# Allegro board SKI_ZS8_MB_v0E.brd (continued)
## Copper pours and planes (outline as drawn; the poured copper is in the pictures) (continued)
DDR_VTTREF on TOP (solid shape): 197.87,58.57 197.87,57.56 197.79,57.48 197.33,57.48 197.23,57.58 197.23,57.68 196.24,58.67 196.14,58.67 195.99,58.83 195.99,59.61 196.01,59.64 196.8,59.64
ECAGND on TOP (solid shape): 46.86,28.96 46.86,27.18 46.74,27.05 44.58,27.05 43.05,28.57 43.05,28.92 43.12,29.15 43.05,29.38 43.05,29.46 43.37,29.78 43.45,29.81 43.52,29.77 44.02,29.7 44.1,30.19 44.09,30.3 44.18,30.35 45.47,30.35
L_SPK+ on TOP (solid shape): 22.4,7.47 22.4,6.83 22.17,6.6 19.56,6.6 19.3,6.86 19.3,7.75 19.43,7.87 22,7.87
L_SPK+ on IN3 (solid shape): 33.45,16.92 33.45,15.47 33.16,15.18 32.58,15.18 32.44,15.32 32.44,16.31 33.15,17.02 33.35,17.02
L_SPK+ on IN3 (solid shape): 23.11,7.87 23.11,6.98 22.99,6.86 22.48,6.86 22.24,6.83 22.02,6.73 20.83,6.73 20.45,7.11 20.45,7.75 20.7,8 22.99,8
L_SPK- on TOP (solid shape): 19.3,6.2 19.34,6.24 19.39,6.23 19.4,6.22 22.17,6.22 22.43,5.96 22.43,5.4 22.23,5.21 19.56,5.21 19.3,5.46
L_SPK- on IN3 (solid shape): 22.99,6.22 22.99,5.33 22.86,5.21 20.57,5.21 20.32,5.46 20.32,6.1 20.57,6.35 22.86,6.35
L_SPK- on IN3 (solid shape): 34.51,17.08 34.51,15.15 34.5,15.15 34.8,14.85 34.8,14.35 34.54,14.1 33.91,14.1 33.83,14.17 33.83,17.07 33.99,17.22 34.37,17.22
LCD_VCC on TOP (solid shape): 25.32,77.94 25.45,77.92 25.59,77.94 28.56,77.94 30.31,76.19 32.31,76.19 32.96,75.55 32.96,74.69 32.72,74.46 26.1,74.46 25.52,75.05 23.26,75.05 23.01,75.3 21.73,75.3 20.39,76.65 20.39,77.79 20.54,77.94
LCD_VCC on BOTTOM (solid shape): 32.84,77.71 32.84,76.24 32.79,76.19 32.79,75.15 32.44,74.79 31.14,74.79 30.86,75.07 30.86,75.66 31.62,76.42 32.62,76.42 32.62,77.54 32.36,77.54 32.36,76.42 32.11,76.42 32.11,77.53 32.11,77.54 31.85,77.54 31.85,76.42 31.62,76.42 31.62,77.76 31.65,77.79 32.77,77.79
LCD_VCC_S on TOP (solid shape): 19.11,82.63 19.11,81.39 19.43,81.07 19.43,78.49 19.81,78.11 19.81,76.58 19.68,76.45 18.54,76.45 18.53,76.47 18.08,76.47 17.64,76.9 17.64,80.56 18.58,81.5 18.58,82.63 18.75,82.8 18.94,82.8
LCD_VIN on TOP (solid shape): 23.18,74.99 23.18,72.97 23.98,72.17 23.98,66.23 23.72,65.98 23.09,65.98 22.87,66.05 22.65,65.98 21.92,65.98 21.67,66.23 21.67,70.03 21.66,70.03 21.66,70.56 21.72,70.63 21.74,70.72 21.74,71.02 21.7,71.14 21.59,71.21 20.01,72.8 20.01,74.95 20.26,75.2 22.97,75.2
LCD_VIN on BOTTOM (solid shape): 27.36,77.81 27.36,74.89 25.96,73.49 25.92,73.46 25.89,73.46 25.87,73.46 25.84,73.47 25.82,73.48 25.78,73.54 25.75,73.58 25.72,73.62 25.68,73.66 25.63,73.69 25.58,73.71 25.53,73.72 25.48,73.73 25.43,73.73 25.38,73.72 25.33,73.7 25.28,73.67 25.24,73.64 25.2,73.61 25.17,73.56 25.14,73.52 25.12,73.47 25.11,73.42 25.11,73.36 25.11,73.31 25.12,73.27 25.12,73.24 25.11,73.21 25.09,73.19 25.07,73.17 25.04,73.16 25.02,73.16 22.71,73.16 22.5,73.37 22.5,75.32 22.68,75.5 24.72,75.5 25.6,76.39 25.6,76.43 27.11,76.43 27.11,77.53 26.86,77.53 26.86,76.43 26.61,76.43 26.61,77.53 26.36,77.53 26.36,76.43 26.11,76.43 26.11,77.53 25.86,77.53 25.86,76.43 25.6,76.43 25.6,77.87 25.75,77.94 27.23,77.94
R_SPK+ on TOP (solid shape): 19.38,3.5 19.42,3.52 19.45,3.5 19.53,3.43 21.75,3.43 21.84,3.33 21.84,2.67 21.59,2.41 19.68,2.41 19.3,2.79 19.3,3.43
R_SPK+ on IN3 (solid shape): 22.86,3.3 22.86,2.41 22.61,2.16 20.57,2.16 20.19,2.54 20.19,3.17 20.45,3.43 22.73,3.43
R_SPK+ on IN3 (solid shape): 36.34,17.13 36.49,17.05 36.67,17.05 37.83,15.89 37.83,15.76 37.52,15.44 36.81,15.44 36.2,16.06 36.2,16.74 36.19,16.87 36.16,17.03 36.27,17.14 36.33,17.14
R_SPK- on TOP (solid shape): 19.3,4.8 19.34,4.85 19.39,4.83 19.4,4.83 22.28,4.83 22.42,4.69 22.42,3.86 22.36,3.81 19.68,3.81 19.3,4.19
R_SPK- on IN3 (solid shape): 23.11,4.7 23.11,3.94 22.99,3.81 22.35,3.81 22.33,3.81 20.57,3.81 20.45,3.94 20.45,4.57 20.7,4.83 22.99,4.83
R_SPK- on IN3 (solid shape): 35.76,17.98 35.76,15.83 35.91,15.69 35.91,15.36 35.8,15.26 35.22,15.26 34.98,15.5 34.98,17.78 35.23,18.03 35.71,18.03
RING2 on TOP (solid shape): 22.63,25.63 22.63,24.36 22.38,24.1 20.73,24.1 20.6,24.23 20.6,25.63 20.85,25.88 22.38,25.88
RING2 on BOTTOM (solid shape): 36.35,26.52 36.35,25.1 36.17,24.92 34.85,24.92 34.75,25.02 34.75,25.5 35.31,26.06 35.31,26.59 35.36,26.64 36.22,26.64
RING2 on IN3 (solid shape): 22.63,25.63 22.63,24.36 22.38,24.1 20.73,24.1 20.6,24.23 20.6,25.63 20.85,25.88 22.38,25.88
RING2 on IN3 (solid shape): 36.35,26.52 36.35,25.1 36.17,24.92 34.85,24.92 34.75,25.02 34.75,25.5 35.31,26.06 35.31,26.59 35.36,26.64 36.22,26.64
RING2_R on TOP (solid shape): 20.22,26.01 20.22,24.69 19.86,24.33 19.18,24.33 18.94,24.57 16.95,24.57 16.64,24.89 16.64,25.91 16.84,26.11 20.12,26.11
RING2_R on IN3 (solid shape): 18.95,26.52 18.95,25.25 18.69,24.99 17.04,24.99 16.66,25.37 16.66,26.39 17.04,26.77 18.69,26.77
SLEEVE on TOP (solid shape): 22.81,17.32 22.81,16.69 22.43,16.31 20.65,16.31 20.4,16.56 20.4,17.45 20.78,17.83 22.3,17.83
SLEEVE on BOTTOM (solid shape): 34.29,26.67 34.75,26.67 34.82,26.59 34.82,26.03 33.91,25.12 33.01,25.12 32.35,25.78 32.35,26.75 32.39,26.79 33.66,26.79 33.66,26.8 34.16,26.8
SLEEVE on IN3 (solid shape): 24.46,17.45 24.46,16.69 24.21,16.43 21.79,16.43 21.41,16.81 21.41,17.7 21.79,18.08 23.83,18.08
SLEEVE on IN3 (solid shape): 34.29,26.42 34.29,25.4 34.16,25.27 32.26,25.27 32,25.53 32,26.42 32.38,26.8 33.91,26.8
SLEEVE_R on TOP (solid shape): 20.02,17.42 20.02,16.03 19.82,15.83 17.99,15.83 17.44,16.38 17.09,16.38 16.94,16.54 16.94,17.25 17.01,17.31 18.94,17.31 19.09,17.46 19.98,17.46
SLEEVE_R on IN3 (solid shape): 19.25,16.81 19.25,15.67 19,15.42 17.73,15.42 17.35,15.8 17.35,16.69 17.6,16.94 19.13,16.94
SPK_L+ on TOP (solid shape): 17.12,8 17.14,8 17.15,7.98 17.63,7.73 18.16,7.85 18.19,7.86 18.21,7.85 18.49,7.74 18.78,7.73 18.79,7.74 18.81,7.73 18.92,7.62 18.92,6.73 18.8,6.6 15.04,6.6 14.93,6.72 14.93,7.81 15.11,8
SPK_L+ on BOTTOM (solid shape): 18.03,9.27 18.03,8.89 17.99,8.81 17.89,8.8 17.37,8.48 17.89,8.16 17.99,8.16 18.03,8.07 18.03,6.98 17.65,6.6 16.81,6.6 16.45,6.97 16.45,9.46 16.51,9.52 17.78,9.52
SPK_L- on TOP (solid shape): 18.75,6.22 18.78,6.21 18.8,6.17 18.8,5.46 18.67,5.33 14.94,5.33 14.87,5.4 14.87,6.11 14.99,6.22
SPK_L- on BOTTOM (solid shape): 15.99,9.49 15.99,6.89 16.66,6.22 17.25,6.22 17.48,5.99 17.48,5.51 17.25,5.28 15.78,5.28 15.21,5.86 15.21,9.49 15.22,9.5 15.24,9.5 15.98,9.5
SPK_R+ on TOP (solid shape): 18.8,3.3 18.8,2.79 18.54,2.54 15.11,2.54 14.9,2.75 14.9,3.44 15.01,3.56 18.54,3.56
SPK_R+ on BOTTOM (solid shape): 13.49,9.45 13.49,4.34 14.38,3.45 17.09,3.45 17.35,3.2 17.35,2.34 17.22,2.21 14.05,2.21 12.67,3.58 12.67,9.47 12.7,9.5 13.44,9.5
SPK_R- on TOP (solid shape): 18.75,4.95 18.78,4.94 18.8,4.9 18.8,4.06 18.67,3.94 14.99,3.94 14.85,4.07 14.85,4.89 14.91,4.95
SPK_R- on BOTTOM (solid shape): 14.74,9.51 14.74,5.78 15.62,4.9 16.94,4.9 17.14,4.7 17.14,4.03 16.95,3.84 14.99,3.84 13.96,4.86 13.96,9.52 14.73,9.52
VA on BOTTOM (solid shape): 198.12,60.64 199.96,60.64 200.15,60.45 200.15,56.26 199.77,55.88 195.71,55.88 195.58,56.01 195.58,56.9 195.81,57.13 196.24,57.13 196.47,57.35 196.47,60.11 197.31,60.11 197.31,60.05 197.33,59.99 197.35,59.94 197.36,59.91 197.36,59.21 197.36,59.19 197.36,59.13 197.37,59.07 197.38,59.01 197.4,58.96 197.43,58.91 197.47,58.86 197.51,58.82 197.56,58.79 197.61,58.76 197.67,58.74 197.72,58.73 197.78,58.72 197.84,58.73 197.9,58.74 197.95,58.76 198,58.78 198.05,58.81 198.1,58.85 198.13,58.9 198.17,58.94 198.19,59 198.21,59.05 198.22,59.11 198.22,59.17 198.22,59.23 198.2,59.28 198.18,59.34 198.17,59.36 198.17,60.09 198.17,60.12 198.17,60.18 198.16,60.24 198.14,60.29 198.11,60.35 198.07,60.4 198.03,60.44 197.99,60.48 197.94,60.51 197.88,60.53 197.82,60.55 197.76,60.55 197.7,60.55 197.65,60.54 197.59,60.53 197.53,60.5 197.48,60.47 197.44,60.43 197.4,60.39 197.37,60.34 197.34,60.29 197.32,60.23 197.31,60.17 197.31,60.11 196.47,60.11 196.47,60.58 196.63,60.74 198.02,60.74
VA1 on TOP (solid shape): 205.59,56.9 206.63,56.9 206.76,56.77 206.76,55.02 204.89,53.15 203.14,53.15 202.02,52.03 200.42,52.03 200.01,52.44 199.66,52.44 199.46,52.24 199.46,51.88 199.25,51.68 198.02,51.68 197.87,51.83 197.87,53.65 203.51,53.65 203.51,53.59 203.53,53.54 203.55,53.49 203.58,53.45 203.61,53.4 203.65,53.37 203.69,53.34 203.74,53.31 203.8,53.3 203.85,53.29 203.9,53.29 203.96,53.3 204.01,53.31 204.06,53.34 204.1,53.37 204.14,53.4 204.18,53.45 204.2,53.49 204.23,53.54 204.24,53.59 204.24,53.65 204.24,53.7 204.23,53.75 204.22,53.8 204.19,53.85 204.16,53.9 204.12,53.94 204.08,53.97 204.03,53.99 203.98,54.01 203.93,54.03 203.88,54.03 203.82,54.03 203.77,54.01 203.72,53.99 203.67,53.97 203.63,53.94 203.59,53.9 203.56,53.85 203.54,53.8 203.52,53.75 203.51,53.7 203.51,53.65 197.87,53.65 197.87,54.14 200.13,56.41 201.32,56.41 202,57.09 204.61,57.09 204.74,57.22 205.27,57.22
VA1 on BOTTOM (solid shape): 199.41,55.1 199.41,51.83 197.36,49.78 193.64,49.78 193.48,49.94 193.48,55.05 193.68,55.25 199.26,55.25
VA2 on BOTTOM (solid shape): 192.51,53.57 192.51,47.34 192.28,47.12 186.44,47.12 186.31,47.24 186.31,52.7 186.44,52.83 187.71,52.83 188.72,53.85 192.23,53.85
VRTC1 on TOP (solid shape): 82.45,46.74 82.45,45.82 82.68,45.59 82.68,44.15 82.58,44.04 81.53,44.04 81.15,44.42 81.15,46.74 81.41,46.99 82.2,46.99
VRTC1 on BOTTOM (solid shape): 81.89,46.85 82.49,46.85 82.55,46.79 82.55,45.97 82.42,45.85 81.28,45.85 81.25,45.87 80.73,45.87 80.41,46.19 80.41,46.73 80.67,46.99 81.75,46.99
VRTC2 on TOP (solid shape): 84.71,46.61 84.71,44.15 84.61,44.04 83.54,44.04 83.46,44.12 83.46,45.75 83.67,45.95 83.67,46.71 83.82,46.86 84.45,46.86
VRTC2 on BOTTOM (solid shape): 84.84,46.48 84.84,45.08 84.45,44.7 83.82,44.7 83.69,44.83 83.69,46.61 83.95,46.86 84.45,46.86
N03288 on TOP (solid shape): 206.76,60.33 206.76,58.04 206.19,57.47 203.2,57.47 203.07,57.6 203.07,58.67 204.98,60.58 206.5,60.58
N05646 on TOP (solid shape): 209.84,57.11 209.84,56.3 209.04,55.5 207.28,55.5 207.09,55.69 207.09,55.8 207.98,55.8 207.98,56.81 207.7,56.81 207.7,55.8 207.09,55.8 207.09,57.61 207.26,57.78 209.17,57.78
N05802 on BOTTOM (solid shape): 124.84,11.68 124.84,10.16 125.22,9.78 125.22,3.94 125.09,3.81 120.65,3.81 120.52,3.94 120.52,10.88 120.22,11.19 120.22,11.38 120.65,11.81 124.71,11.81
N90734 on BOTTOM (solid shape): 105.86,18.8 105.86,12.89 104.9,11.94 100.71,11.94 100.46,12.19 100.46,17.91 101.6,19.05 105.6,19.05
N243495 on BOTTOM (solid shape): 186.06,52.7 186.06,47.24 185.93,47.12 180.21,47.12 180.09,47.24 180.09,52.7 180.21,52.83 185.93,52.83
N19426582 on TOP (solid shape): 56.52,79.13 56.52,74.3 57.02,73.79 57.02,72.01 56.9,71.88 53.34,71.88 52.7,72.52 52.7,79.25 53.03,79.57 56.07,79.57
N19426582 on BOTTOM (solid shape): 56.13,79.13 56.13,74.04 56.01,73.91 53.09,73.91 52.7,74.3 52.7,77.79 53.03,78.11 53.03,79.57 53.28,79.82 55.44,79.82
N19439774 on TOP (solid shape): 49.4,79.25 49.4,72.01 49.28,71.88 45.59,71.88 45.47,72.01 45.47,76.45 45.85,76.83 45.85,79.25 46.17,79.57 49.09,79.57
N19439774 on BOTTOM (solid shape): 49.4,79.51 49.4,74.3 45.1,69.99 42.84,69.99 42.64,70.19 42.64,77.33 45,79.7 49.22,79.7
N106400399 on TOP (solid shape): 184.66,103.4 184.66,102.67 184.53,102.54 182.75,102.54 182.63,102.67 182.63,103.4 182.65,103.43 184.63,103.43

Small or netless copper shapes (teardrops, artwork), in the pictures only: 28 on TOP, 39 on BOTTOM, 6 on IN1, 65 on IN2, 1 on IN3

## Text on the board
Ref Des/Silkscreen Bottom: DA0ZS8MB8E0 REV:E
User.Comments: 24.0x94.0
Ref Des/Silkscreen Top: DA0ZS8MB8E0 REV:E | MODEL:ZS8
User.12: GND | AGND_ADO | +3V3 | +5V_S5 | VIN | +3V3_PCU | +3V3_S5 | +1V05_S5 | +VCCIN
User.26: AGND_ADO | GND
User.27: AGND_ADO | GND
User.45: FIGURE | TYPE | Circle | Oblong | SIZE | 8.0 | 10.0 | 12.0 | 14.0 | 20.0 | 22.0 | 32.0 | 102.0 | 142.0 | 165.0 | 39.0 | 40.0 | 43.0 | 55.0 | 63.0 | 87.0 | 150.0 | 55.0x24.0 | 55.0x43.0 | 59.0x24.0 | 69.0x20.0 | 91.0x28.0 | 91.0x43.0 | 98.0x79.0 | DRILL CHART: TOP to BOTTOM | ALL UNITS ARE IN MILS | PLATED | NON-PLATED | ROTATION | - | 0.000 | 90.000 | QTY | 516 | 3274 | 23 | 346 | 68 | 19 | 18 | 8 | 1 | 2 | 3 | 4 | 4289 | 7 | 27 | TOTAL HOLES:
